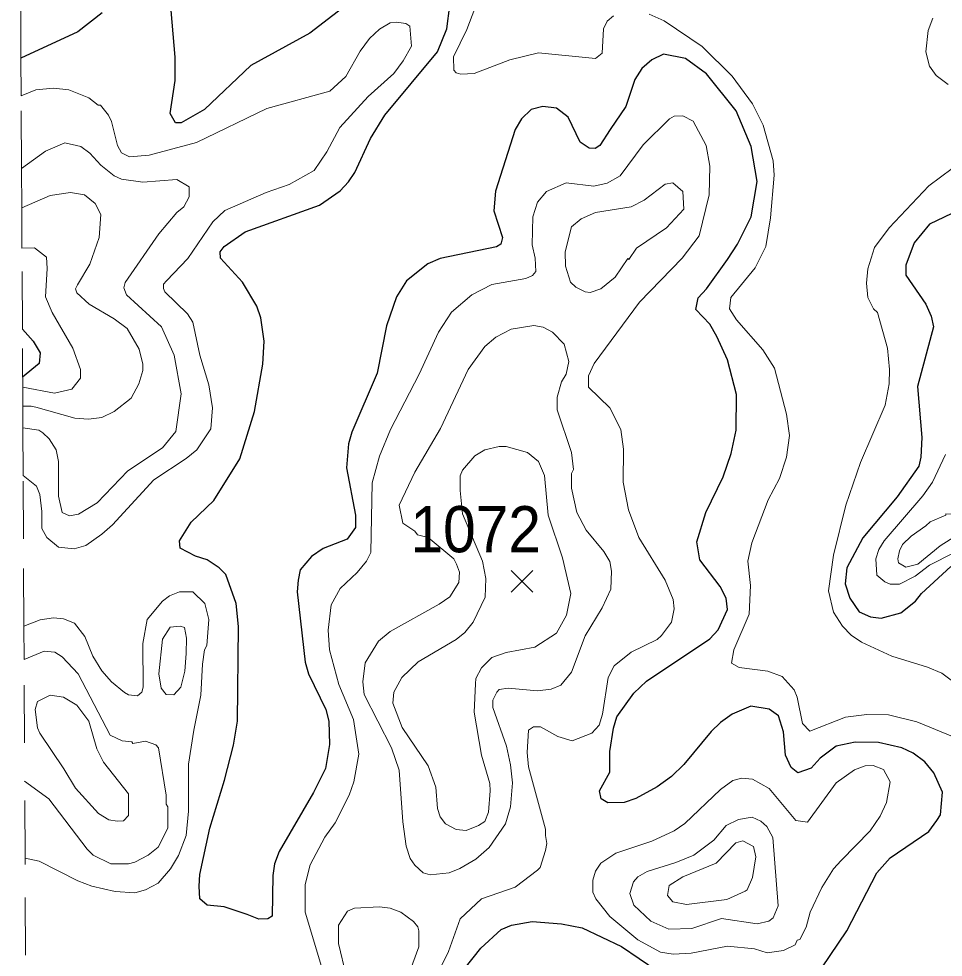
# Model space of a CAD drawing. Extents: x 423 to 448.8, y 7456.3 to 7484.
# Drawn here: x 423.031 to 424.633, y 7474.164 to 7475.791 of the extents above; entities that cross this region are included whole.
import ezdxf
from ezdxf.enums import TextEntityAlignment as Align

# ---------------------------------------------------------------- set-up
doc = ezdxf.new("R2010")
doc.units = 0
doc.header["$LTSCALE"] = 0.032
doc.linetypes.add('SHORT_DASHED', pattern=[2.7, 1.5, -1.2])
for name, color, linetype, lineweight in [('1', 7, 'Continuous', 25), ('2', 7, 'Continuous', 13), ('21', 7, 'Continuous', 25), ('22', 7, 'SHORT_DASHED', 13)]:
    doc.layers.add(name, color=color, linetype=linetype, lineweight=lineweight)
doc.layers.add('61', color=7, linetype='Continuous')

msp = doc.modelspace()

# ---------------------------------------------------------------- linework, layer by layer
at = {"layer": '1'}
for points in [[(423.6621, 7475.8645), (423.5353, 7475.7663), (423.4332, 7475.7106), (423.3527, 7475.634), (423.3125, 7475.6108), (423.3024, 7475.6108), (423.2932, 7475.6271), (423.3017, 7475.6843), (423.3017, 7475.7246), (423.2916, 7475.8468)], [(423.362, 7474.388), (423.3875, 7474.4716), (423.403, 7474.5319), (423.41, 7474.5737), (423.4115, 7474.7376), (423.4076, 7474.7778), (423.3898, 7474.8281), (423.3783, 7474.8397), (423.3574, 7474.8536), (423.3373, 7474.8598), (423.3109, 7474.8737), (423.3094, 7474.8861), (423.3295, 7474.9186), (423.369, 7474.9565), (423.4138, 7475.0284), (423.4394, 7475.1104), (423.4541, 7475.1924), (423.4564, 7475.2326), (423.4502, 7475.2729), (423.4432, 7475.293), (423.4185, 7475.3347), (423.3806, 7475.3765), (423.3798, 7475.3873), (423.3867, 7475.3966), (423.4231, 7475.4221), (423.5523, 7475.4685), (423.5879, 7475.4933), (423.6025, 7475.5087), (423.6134, 7475.525), (423.6405, 7475.5838), (423.6652, 7475.624), (423.7565, 7475.7338), (423.7727, 7475.7741), (423.7781, 7475.8143)], [(423.1756, 7475.8019), (423.1331, 7475.7686), (423.0348, 7475.7229)], [(424.267, 7474.586), (424.2469, 7474.5713), (424.2306, 7474.5558), (424.1834, 7474.4986), (424.1618, 7474.4777), (424.137, 7474.4599), (424.0999, 7474.4398), (424.0798, 7474.4329), (424.0519, 7474.4321), (424.0403, 7474.439), (424.0372, 7474.453), (424.055, 7474.4854), (424.055, 7474.5211), (424.0612, 7474.5613), (424.0674, 7474.5814), (424.0968, 7474.6224), (424.1184, 7474.6433), (424.2283, 7474.7167), (424.243, 7474.7322), (424.2592, 7474.767), (424.2569, 7474.7871), (424.2461, 7474.8072), (424.2113, 7474.8536), (424.2059, 7474.8846), (424.2213, 7474.9356), (424.2515, 7474.9975), (424.2654, 7475.0377), (424.2739, 7475.0779), (424.2747, 7475.1398), (424.2592, 7475.2002), (424.2407, 7475.2404), (424.2283, 7475.262), (424.2043, 7475.2875), (424.2082, 7475.3076), (424.2229, 7475.3231), (424.2592, 7475.3742), (424.2762, 7475.4005), (424.3002, 7475.4477), (424.3103, 7475.5095), (424.3002, 7475.5699), (424.2739, 7475.6317), (424.2229, 7475.6959), (424.1865, 7475.7222), (424.1479, 7475.7299), (424.1278, 7475.7199), (424.1107, 7475.7052), (424.0984, 7475.6858), (424.0829, 7475.6395), (424.0558, 7475.5993), (424.038, 7475.5714), (424.0295, 7475.5667), (424.0195, 7475.5668), (424.004, 7475.5776), (423.9831, 7475.6209), (423.963, 7475.6363), (423.939, 7475.6394), (423.9189, 7475.634), (423.9019, 7475.6178), (423.8911, 7475.5993), (423.857, 7475.4925), (423.8539, 7475.4585), (423.8694, 7475.4121), (423.8663, 7475.4005), (423.8586, 7475.3958), (423.7611, 7475.3757), (423.7395, 7475.3664), (423.7031, 7475.337), (423.6853, 7475.3092), (423.6683, 7475.2589), (423.6521, 7475.177), (423.608, 7475.0749), (423.6026, 7475.0547), (423.5987, 7475.013), (423.6142, 7474.931), (423.6142, 7474.9093), (423.6002, 7474.8892), (423.5585, 7474.8729), (423.5384, 7474.8591), (423.5183, 7474.8358), (423.5152, 7474.8181), (423.5136, 7474.798), (423.5275, 7474.6757), (423.533, 7474.6556), (423.5631, 7474.5938), (423.5685, 7474.5737), (423.5693, 7474.5334), (423.5623, 7474.4917), (423.5414, 7474.4499), (423.4819, 7474.3478), (423.4742, 7474.3261), (423.4711, 7474.306), (423.4703, 7474.2356), (423.4626, 7474.231), (423.4471, 7474.2302), (423.427, 7474.2387), (423.3868, 7474.2519), (423.3574, 7474.2549), (423.345, 7474.2658), (423.3435, 7474.2875), (423.345, 7474.3076), (423.362, 7474.388)], [(424.6599, 7475.4593), (424.6088, 7475.4353), (424.5825, 7475.4028), (424.5678, 7475.3641), (424.5678, 7475.3471), (424.6026, 7475.2968), (424.6119, 7475.276), (424.6158, 7475.2574), (424.588, 7475.1537), (424.5957, 7475.0656), (424.5941, 7475.0315), (424.5903, 7475.016), (424.5531, 7474.9627), (424.4936, 7474.8915), (424.4657, 7474.8397), (424.4627, 7474.8118), (424.4712, 7474.7871), (424.4874, 7474.7631), (424.5068, 7474.7546), (424.5253, 7474.7523), (424.5593, 7474.7616), (424.5848, 7474.7817), (424.5949, 7474.7948), (424.6459, 7474.842)], [(423.0372, 7475.2535), (423.0557, 7475.2326), (423.0681, 7475.2125), (423.0665, 7475.194), (423.0377, 7475.1701)], [(424.4227, 7474.1463), (424.4658, 7474.2101), (424.5175, 7474.3107), (424.5408, 7474.3369), (424.608, 7474.3826), (424.622, 7474.4012), (424.6282, 7474.4112), (424.6313, 7474.4507), (424.6166, 7474.4839), (424.6011, 7474.5032), (424.581, 7474.518), (424.5609, 7474.5272), (424.5207, 7474.5365), (424.4805, 7474.5373), (424.4472, 7474.5303), (424.4193, 7474.5094), (424.4038, 7474.4924), (424.3807, 7474.4839), (424.3691, 7474.4932), (424.3598, 7474.5149), (424.3559, 7474.5551), (424.3474, 7474.5829), (424.3311, 7474.5945), (424.2994, 7474.5999), (424.267, 7474.586)], [(423.8029, 7474.1436), (423.8315, 7474.1799), (423.8671, 7474.2124), (423.8849, 7474.2202), (423.9205, 7474.2263), (423.9715, 7474.2225), (424.0071, 7474.2155), (424.0752, 7474.183), (424.1672, 7474.1204)]]:
    msp.add_lwpolyline(points, dxfattribs=at)
at = {"layer": '2'}
for points in [[(423.8261, 7475.8212), (423.8075, 7475.7725), (423.7843, 7475.7253), (423.7851, 7475.7021), (423.7889, 7475.6975), (423.7967, 7475.6952), (423.8199, 7475.6967), (423.8818, 7475.7199), (423.9313, 7475.7323), (424.0303, 7475.7222), (424.0419, 7475.7315), (424.0442, 7475.7741), (424.0504, 7475.7872), (424.0612, 7475.7965)], [(424.1231, 7475.7996), (424.1494, 7475.7879), (424.2151, 7475.7431), (424.2669, 7475.692), (424.3025, 7475.6441), (424.3211, 7475.607), (424.3381, 7475.5451), (424.3397, 7475.5204), (424.3335, 7475.4461), (424.3257, 7475.3966), (424.3072, 7475.3595), (424.2646, 7475.3084), (424.2623, 7475.2883), (424.2747, 7475.2697), (424.3203, 7475.2172), (424.3404, 7475.1854), (424.3613, 7475.1058), (424.3667, 7475.0687), (424.3613, 7475.0315), (424.3489, 7474.9944), (424.3296, 7474.9573), (424.301, 7474.883), (424.294, 7474.8513), (424.2987, 7474.8088), (424.2964, 7474.7592), (424.27, 7474.6974), (424.2662, 7474.6742), (424.2794, 7474.6665), (424.3289, 7474.6603), (424.3536, 7474.651), (424.3745, 7474.6278)], [(424.6413, 7475.6774), (424.6204, 7475.6928), (424.6088, 7475.7091), (424.6026, 7475.7338), (424.6065, 7475.771), (424.615, 7475.7926)], [(423.0352, 7475.6575), (423.0604, 7475.6681), (423.0913, 7475.6712), (423.1176, 7475.6681), (423.1524, 7475.6542), (423.1686, 7475.6418), (423.1725, 7475.6418), (423.1864, 7475.624), (423.1918, 7475.6132), (423.2019, 7475.5714), (423.2088, 7475.559), (423.2228, 7475.5521), (423.2568, 7475.5551), (423.3388, 7475.5768), (423.461, 7475.6356), (423.5701, 7475.6657), (423.5979, 7475.6913), (423.6227, 7475.7354), (423.6389, 7475.757), (423.6559, 7475.7733), (423.6745, 7475.7841), (423.6853, 7475.7857), (423.7016, 7475.7833), (423.7085, 7475.7787), (423.7116, 7475.7439), (423.6969, 7475.7184), (423.6807, 7475.6967), (423.6366, 7475.6565), (423.5871, 7475.6031), (423.5647, 7475.5606), (423.543, 7475.5281), (423.4997, 7475.5041), (423.4595, 7475.4902), (423.3883, 7475.4592), (423.3674, 7475.4391), (423.3241, 7475.3757), (423.287, 7475.337), (423.2819, 7475.3313), (423.2816, 7475.3239), (423.2839, 7475.3177), (423.3234, 7475.2798), (423.3326, 7475.2651), (423.345, 7475.2079), (423.3605, 7475.1568), (423.3667, 7475.1166), (423.3636, 7475.0802), (423.3396, 7475.0439), (423.321, 7475.0292), (423.2653, 7474.9921), (423.1934, 7474.9139), (423.1749, 7474.8977), (423.147, 7474.8784), (423.1269, 7474.8722), (423.0998, 7474.8753), (423.0797, 7474.8923), (423.0712, 7474.9077), (423.0712, 7474.9372), (423.0673, 7474.9666), (423.0619, 7474.9812), (423.0385, 7474.9994)], [(423.7518, 7474.1266), (423.7758, 7474.1745), (423.7959, 7474.231), (423.833, 7474.2658), (423.8911, 7474.2859), (423.9298, 7474.3153), (423.9344, 7474.3199), (423.9437, 7474.3493), (423.946, 7474.3617), (423.9437, 7474.3756), (423.9437, 7474.3865), (423.9142, 7474.4948), (423.9119, 7474.5195), (423.9142, 7474.5581), (423.9228, 7474.5636), (423.9351, 7474.5636), (423.9653, 7474.5473), (423.9901, 7474.5396), (424.0241, 7474.5528), (424.0365, 7474.5667), (424.0427, 7474.586), (424.052, 7474.6495), (424.0627, 7474.6696), (424.0922, 7474.6935), (424.137, 7474.7152), (424.1447, 7474.7221), (424.1617, 7474.7454), (424.1664, 7474.7686), (424.1648, 7474.7848), (424.151, 7474.8181), (424.1053, 7474.8923), (424.0875, 7474.9403), (424.0782, 7474.9882), (424.079, 7475.0455), (424.0744, 7475.0795), (424.055, 7475.1166), (424.0179, 7475.1529), (424.0179, 7475.1723), (424.028, 7475.194), (424.1068, 7475.2999), (424.1803, 7475.3765), (424.2097, 7475.4151), (424.2275, 7475.4863), (424.2283, 7475.5358), (424.2221, 7475.5714), (424.1997, 7475.6139), (424.1819, 7475.6232), (424.1664, 7475.6224), (424.1587, 7475.6178), (424.113, 7475.5729), (424.0728, 7475.5188), (424.0504, 7475.5064), (424.0272, 7475.501), (423.9793, 7475.5072), (423.9452, 7475.4917), (423.9297, 7475.4732), (423.922, 7475.4477), (423.9205, 7475.3997), (423.9259, 7475.3765), (423.9267, 7475.3533), (423.9212, 7475.3463), (423.9096, 7475.3409), (423.8509, 7475.3309), (423.816, 7475.313), (423.7805, 7475.2829), (423.758, 7475.2481), (423.7248, 7475.1754), (423.6752, 7475.0795), (423.6559, 7475.0331), (423.6436, 7474.9867), (423.6412, 7474.866), (423.6335, 7474.8513), (423.6172, 7474.8312), (423.5878, 7474.8034), (423.5724, 7474.7755), (423.567, 7474.7314), (423.5693, 7474.6974), (423.5855, 7474.6371)], [(423.0358, 7475.5317), (423.0774, 7475.5621), (423.1106, 7475.5761), (423.1385, 7475.5698), (423.1539, 7475.5582), (423.1733, 7475.5373), (423.1965, 7475.5188), (423.2089, 7475.5134), (423.246, 7475.508), (423.3048, 7475.5126), (423.3264, 7475.5002), (423.3264, 7475.4824), (423.3172, 7475.4654), (423.3048, 7475.4554), (423.2738, 7475.4183), (423.2151, 7475.3339), (423.2131, 7475.3247), (423.2174, 7475.313), (423.2785, 7475.2574), (423.3001, 7475.2079), (423.3125, 7475.1414), (423.3032, 7475.0756), (423.28, 7475.0478), (423.2197, 7475.0075), (423.1671, 7474.9519), (423.1346, 7474.9325), (423.1191, 7474.9294), (423.106, 7474.9356), (423.0998, 7474.9635), (423.0998, 7475.0238), (423.096, 7475.0439), (423.0835, 7475.0632), (423.0728, 7475.0733), (423.0658, 7475.0779), (423.0381, 7475.082)], [(424.6537, 7474.6394), (424.6305, 7474.6571), (424.6058, 7474.6672), (424.5439, 7474.6866), (424.4912, 7474.7105), (424.4735, 7474.7229), (424.458, 7474.7384), (424.4425, 7474.7624), (424.434, 7474.7995), (424.4425, 7474.8614), (424.4642, 7474.948), (424.4897, 7475.0223), (424.5322, 7475.1213), (424.5392, 7475.1584), (424.54, 7475.1831), (424.5361, 7475.2203), (424.5191, 7475.2821), (424.5121, 7475.2883), (424.5021, 7475.3084), (424.4998, 7475.3332), (424.5021, 7475.3579), (424.5137, 7475.3951), (424.5392, 7475.4291), (424.6081, 7475.5018), (424.6483, 7475.532)], [(423.0362, 7475.4635), (423.0851, 7475.4848), (423.1207, 7475.4902), (423.1447, 7475.4863), (423.1632, 7475.4709), (423.1733, 7475.4523), (423.1702, 7475.4121), (423.1539, 7475.3657), (423.133, 7475.3301), (423.1291, 7475.3231), (423.1315, 7475.3161), (423.1532, 7475.2968), (423.1965, 7475.2713), (423.2189, 7475.2543), (423.2398, 7475.2187), (423.246, 7475.1924), (423.246, 7475.1816), (423.239, 7475.1584), (423.2259, 7475.1336), (423.1965, 7475.1104), (423.1749, 7475.1003), (423.1516, 7475.0973), (423.1284, 7475.0988), (423.0603, 7475.1182), (423.0523, 7475.1199), (423.0379, 7475.1197)], [(423.0365, 7475.3936), (423.058, 7475.3943), (423.0789, 7475.3781), (423.08, 7475.3584), (423.0774, 7475.3092), (423.089, 7475.2821), (423.1245, 7475.2203), (423.1377, 7475.1831), (423.1377, 7475.1684), (423.123, 7475.1491), (423.0929, 7475.1421), (423.0378, 7475.1525)], [(424.6367, 7475.0362), (424.6142, 7474.9882), (424.5972, 7474.9642), (424.5307, 7474.8861), (424.5214, 7474.8714), (424.516, 7474.8552), (424.5175, 7474.8265), (424.5315, 7474.815), (424.5408, 7474.8111), (424.557, 7474.8111), (424.5841, 7474.825), (424.6088, 7474.8443), (424.6931, 7474.8869)], [(423.0398, 7474.7385), (423.0681, 7474.7492), (423.0913, 7474.753), (423.1083, 7474.7508), (423.1276, 7474.7438), (423.1455, 7474.7206), (423.1594, 7474.6866), (423.1748, 7474.661), (423.1918, 7474.6417), (423.2143, 7474.6231), (423.2213, 7474.6193), (423.2367, 7474.6177), (423.2444, 7474.6239), (423.2468, 7474.6324), (423.246, 7474.7082), (423.2537, 7474.75), (423.28, 7474.7817), (423.2924, 7474.791), (423.3094, 7474.798), (423.3326, 7474.798), (423.3535, 7474.7778), (423.3605, 7474.75), (423.3566, 7474.7051), (423.3527, 7474.6974), (423.3496, 7474.6727), (423.3466, 7474.6185), (423.3342, 7474.5582), (423.3249, 7474.4994), (423.3249, 7474.4174), (423.321, 7474.3756), (423.3079, 7474.3408), (423.2939, 7474.3176), (423.2723, 7474.2929), (423.2507, 7474.2813), (423.2321, 7474.2759), (423.1981, 7474.2782), (423.1578, 7474.2875), (423.1331, 7474.2967), (423.0666, 7474.3308), (423.0418, 7474.336)], [(423.0401, 7474.6804), (423.0751, 7474.6951), (423.0936, 7474.6935), (423.106, 7474.685), (423.1338, 7474.6556), (423.1895, 7474.5496), (423.2104, 7474.5396), (423.2267, 7474.5381), (423.2289, 7474.535), (423.2507, 7474.5388), (423.2684, 7474.5326), (423.2731, 7474.5272), (423.2862, 7474.4453), (423.2862, 7474.4298), (423.2893, 7474.4251), (423.2893, 7474.388), (423.2723, 7474.3555), (423.2552, 7474.3416), (423.2321, 7474.3292), (423.2213, 7474.3261), (423.1903, 7474.3261), (423.1601, 7474.3416), (423.1493, 7474.3516), (423.0828, 7474.439), (423.0412, 7474.4699)], [(423.5855, 7474.6371), (423.6111, 7474.5767), (423.6204, 7474.5164), (423.6118, 7474.4685), (423.6033, 7474.4453), (423.5793, 7474.3973), (423.5615, 7474.3726), (423.536, 7474.3246), (423.5275, 7474.2906), (423.5275, 7474.2426), (423.5554, 7474.1483)], [(424.3745, 7474.6278), (424.3799, 7474.6154), (424.3892, 7474.5698), (424.4016, 7474.5566), (424.4634, 7474.5806), (424.5006, 7474.5852), (424.5377, 7474.5845), (424.5872, 7474.5728), (424.6614, 7474.5419)], [(423.6892, 7474.0864), (423.724, 7474.1823), (423.724, 7474.2101), (423.7224, 7474.2171), (423.7147, 7474.2263), (423.6931, 7474.2426), (423.6745, 7474.2495), (423.6559, 7474.2519), (423.6126, 7474.2495), (423.6003, 7474.2442), (423.5848, 7474.2202), (423.5848, 7474.1885), (423.6118, 7474.0771)]]:
    msp.add_lwpolyline(points, dxfattribs=at)
for points in [[(424.0863, 7475.3757), (424.0883, 7475.3742), (424.1014, 7475.3935), (424.1533, 7475.4291), (424.1834, 7475.4615), (424.1819, 7475.4917), (424.1641, 7475.5072), (424.1509, 7475.5049), (424.1146, 7475.477), (424.0922, 7475.4654), (424.0303, 7475.4554), (424.0055, 7475.4445), (423.9885, 7475.4306), (423.9777, 7475.3873), (423.9784, 7475.3626), (423.987, 7475.3347), (423.9962, 7475.3262), (424.0125, 7475.3177), (424.021, 7475.3169), (424.0395, 7475.3231), (424.0643, 7475.3432)], [(423.7897, 7474.8459), (423.7851, 7474.8551), (423.7401, 7474.892), (423.722, 7474.8965), (423.717, 7474.9031), (423.6962, 7474.9171), (423.69, 7474.948), (423.717, 7475.0052), (423.7619, 7475.081), (423.8098, 7475.1831), (423.8385, 7475.2233), (423.8578, 7475.2396), (423.8841, 7475.2535), (423.9236, 7475.2597), (423.9398, 7475.2566), (423.956, 7475.2481), (423.9762, 7475.2272), (423.9839, 7475.1971), (423.9792, 7475.1754), (423.9715, 7475.1622), (423.9638, 7475.1352), (423.9638, 7475.1135), (423.9885, 7475.0393), (423.9924, 7475.0099), (423.9885, 7475.0029), (423.9885, 7474.9774), (423.9978, 7474.9356), (424.014, 7474.9047), (424.045, 7474.8676), (424.055, 7474.8505), (424.0581, 7474.8335), (424.0566, 7474.8026), (424.0419, 7474.7701), (424.0125, 7474.7214), (423.9885, 7474.6587), (423.97, 7474.6363), (423.9537, 7474.6293), (423.9298, 7474.6262), (423.8787, 7474.6308), (423.8632, 7474.6285), (423.8593, 7474.6239), (423.8524, 7474.61), (423.8524, 7474.5976), (423.8763, 7474.5303), (423.8833, 7474.4979), (423.8864, 7474.4669), (423.8833, 7474.4251), (423.8741, 7474.3958), (423.8462, 7474.3547), (423.823, 7474.3346), (423.7952, 7474.3184), (423.7766, 7474.3106), (423.7441, 7474.3075), (423.7317, 7474.3106), (423.717, 7474.3238), (423.7093, 7474.3354), (423.7023, 7474.3571), (423.6962, 7474.3989), (423.69, 7474.4886), (423.6768, 7474.5272), (423.6296, 7474.6201), (423.6273, 7474.6417), (423.6312, 7474.6749), (423.6544, 7474.7121), (423.6745, 7474.7291), (423.7596, 7474.7763), (423.7781, 7474.7894), (423.7936, 7474.8142), (423.7944, 7474.832)], [(423.6953, 7474.5628), (423.6791, 7474.6046), (423.6807, 7474.6239), (423.6946, 7474.6495), (423.7232, 7474.6765), (423.7889, 7474.7152), (423.8037, 7474.7275), (423.8183, 7474.7454), (423.8392, 7474.7887), (423.84, 7474.8212), (423.8346, 7474.8513), (423.8001, 7474.9329), (423.7956, 7474.9734), (423.7959, 7474.9991), (423.7998, 7475.0091), (423.8215, 7475.0338), (423.8385, 7475.0439), (423.8632, 7475.0501), (423.8756, 7475.0501), (423.9127, 7475.0392), (423.9313, 7475.0238), (423.9421, 7474.9998), (423.9483, 7474.931), (423.9731, 7474.8567), (423.9877, 7474.7949), (423.98, 7474.7577), (423.963, 7474.726), (423.9251, 7474.702), (423.8756, 7474.6928), (423.8509, 7474.6842), (423.833, 7474.6664), (423.823, 7474.6479), (423.8222, 7474.6386), (423.8199, 7474.5891), (423.833, 7474.5149), (423.847, 7474.4654), (423.8478, 7474.453), (423.8447, 7474.4159), (423.8385, 7474.3996), (423.8276, 7474.3926), (423.806, 7474.3841), (423.7889, 7474.3857), (423.7704, 7474.3958), (423.7611, 7474.4081), (423.7565, 7474.4221), (423.7534, 7474.4592), (423.7402, 7474.4963)], [(424.6027, 7474.9124), (424.6104, 7474.9194), (424.6375, 7474.931), (424.6375, 7474.9333), (424.6614, 7474.9325), (424.6692, 7474.9286), (424.6723, 7474.9202), (424.6668, 7474.9023), (424.6274, 7474.8776), (424.5887, 7474.8459), (424.5678, 7474.8405), (424.5555, 7474.8482), (424.5539, 7474.8552), (424.557, 7474.8691), (424.5624, 7474.8799), (424.5771, 7474.8946)], [(423.321, 7474.6912), (423.3218, 7474.7175), (423.3179, 7474.736), (423.3109, 7474.7384), (423.2932, 7474.7368), (423.28, 7474.716), (423.2738, 7474.6556), (423.2777, 7474.6309), (423.2862, 7474.62), (423.2994, 7474.6193), (423.3117, 7474.6324), (423.3187, 7474.6603)], [(423.1091, 7474.4909), (423.0673, 7474.5527), (423.0635, 7474.562), (423.0596, 7474.5938), (423.0635, 7474.6076), (423.0851, 7474.6185), (423.1083, 7474.6154), (423.1315, 7474.6015), (423.1524, 7474.5737), (423.1663, 7474.5257), (423.1779, 7474.5025), (423.2212, 7474.4476), (423.2212, 7474.4104), (423.2127, 7474.4011), (423.2012, 7474.4004), (423.1872, 7474.4027), (423.1694, 7474.4135), (423.1292, 7474.4576)], [(424.0658, 7474.3447), (424.1278, 7474.3656), (424.1664, 7474.3834), (424.1849, 7474.3965), (424.2469, 7474.4553), (424.2685, 7474.4708), (424.284, 7474.4746), (424.3026, 7474.4731), (424.3311, 7474.4568), (424.3776, 7474.4012), (424.3977, 7474.3988), (424.4472, 7474.4669), (424.4789, 7474.4893), (424.4975, 7474.4963), (424.5114, 7474.497), (424.5292, 7474.4901), (424.5408, 7474.4684), (424.5346, 7474.4329), (424.5237, 7474.4089), (424.506, 7474.3833), (424.4557, 7474.3323), (424.4425, 7474.3176), (424.4224, 7474.2851), (424.4023, 7474.2426), (424.3953, 7474.2163), (424.3845, 7474.1954), (424.3799, 7474.1939), (424.376, 7474.1861), (424.356, 7474.176), (424.3278, 7474.172), (424.3057, 7474.1792), (424.2592, 7474.1838), (424.1958, 7474.1714), (424.1649, 7474.1699), (424.1432, 7474.173), (424.1038, 7474.1947), (424.055, 7474.2348), (424.031, 7474.2658), (424.0257, 7474.2774), (424.0257, 7474.2983), (424.0303, 7474.3137), (424.0395, 7474.3276)], [(424.096, 7474.2952), (424.1037, 7474.3037), (424.12, 7474.313), (424.1695, 7474.3284), (424.2005, 7474.3416), (424.2352, 7474.3671), (424.2569, 7474.3927), (424.2778, 7474.4035), (424.3018, 7474.4073), (424.3165, 7474.4004), (424.3273, 7474.3911), (424.3373, 7474.3718), (424.3466, 7474.2534), (424.3381, 7474.2325), (424.3304, 7474.2271), (424.3103, 7474.2225), (424.2484, 7474.2318), (424.1974, 7474.214), (424.1571, 7474.2132), (424.1262, 7474.2271), (424.0968, 7474.2549), (424.0898, 7474.2751)], [(424.2894, 7474.2789), (424.2933, 7474.2812), (424.3026, 7474.3029), (424.3079, 7474.3385), (424.3041, 7474.3563), (424.2855, 7474.3663), (424.2732, 7474.3625), (424.2391, 7474.3277), (424.1819, 7474.3037), (424.1579, 7474.289), (424.1548, 7474.2712), (424.1641, 7474.2604), (424.1881, 7474.2557), (424.2577, 7474.2643)]]:
    msp.add_lwpolyline(points, close=True, dxfattribs=at)
at = {"layer": '21'}
for p, q in [((423.8844, 7474.8348), (423.9219, 7474.7973)), ((423.9219, 7474.8348), (423.8844, 7474.7973))]:
    msp.add_line(p, q, dxfattribs=at)
at = {"layer": '22'}
for points in [[(423.0348, 7475.7229), (423.0333, 7476.0195), (423.0323, 7476.2194), (423.0313, 7476.4175), (423.031, 7476.4775)], [(423.0365, 7475.3936), (423.0362, 7475.4546), (423.0362, 7475.4635), (423.0358, 7475.5317), (423.0352, 7475.6575), (423.0348, 7475.7229)], [(423.0398, 7474.7385), (423.0391, 7474.8898), (423.0385, 7474.9994), (423.0381, 7475.082), (423.0379, 7475.1197), (423.0372, 7475.2535), (423.0365, 7475.3936)], [(423.0437, 7473.9682), (423.0419, 7474.325), (423.0418, 7474.336), (423.0401, 7474.6804), (423.0398, 7474.7385)]]:
    msp.add_lwpolyline(points, dxfattribs=at)

# ---------------------------------------------------------------- texts
at = {"layer": '61', "width": 0.95}
msp.add_text('1072', height=0.08, dxfattribs=at).set_placement((423.8227, 7474.8665), align=Align.CENTER)

doc.saveas('drawing.dxf')
